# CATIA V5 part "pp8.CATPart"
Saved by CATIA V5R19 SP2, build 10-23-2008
Part number: pp8
Bounding box of the stored display mesh (mm): x -20 to 20, y 0 to 120, z -75.031 to 75.031
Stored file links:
  C:\Users\Welcome\Documents\thinkm2\pp8.CATPart
  C:\Users\Welcome\Documents\thinkm2\Brasmeca.CATProduct
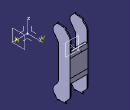
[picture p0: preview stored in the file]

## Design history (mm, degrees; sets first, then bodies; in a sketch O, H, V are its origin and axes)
AxisSystem1: origin (0, 0, 0), X (1, 0, 0), Y (0, 1, 0), Z (0, 0, 1)
Set1
  Line1: linked copy from another document
  Point1: linked copy from another document
Body1 (main body)
  Plane1: type Normal, Curve Line1, RefPoint Point1
  Plane2: type Offset, RefPlane YZ plane of AxisSystem1, Offset 20
  Sketch1 on Plane2, origin (20, 0, 0), H (0, 1, 0), V (0, 0, 1)
    line L1 (115.6767, 19.4458) -> (115.6767, 54.1125)
    line L2 (112.2785, 61.8229) -> (104.423, 69.6832)
    line L3 (104.423, 69.6832) -> (106.9485, 72.2071)
    line L4 (106.9485, 72.2071) -> (88.0918, 72.9515)
    line L5 (88.0918, 72.9515) -> (88.0918, 75.0312)
    line L6 (88.0918, 75.0312) -> (79.7197, 65.0499)
    line L7 (79.5179, 51.5719) -> (86.7623, 42.3901)
    line L8 (89.7249, 33.8522) -> (89.7249, 13.8264)
    arc A1 centre (103.978, 53.5605) radius 11.7118 from (115.6767, 54.1125) to (112.2785, 61.8229) ccw
    arc A2 centre (87.9019, 58.1869) radius 10.6794 from (79.7197, 65.0499) to (79.5179, 51.5719) ccw
    arc A3 centre (75.9411, 33.8522) radius 13.7839 from (86.7623, 42.3901) to (89.7249, 33.8522) cw
    line L9 (89.7249, -33.8522) -> (89.7249, -13.8264)
    arc A4 centre (75.9411, -33.8522) radius 13.7839 from (86.7623, -42.3901) to (89.7249, -33.8522) ccw
    line L10 (79.5179, -51.5719) -> (86.7623, -42.3901)
    arc A5 centre (87.9019, -58.1869) radius 10.6794 from (79.7197, -65.0499) to (79.5179, -51.5719) cw
    line L11 (88.0918, -75.0312) -> (79.7197, -65.0499)
    line L12 (88.0918, -72.9515) -> (88.0918, -75.0312)
    line L13 (106.9485, -72.2071) -> (88.0918, -72.9515)
    line L14 (104.423, -69.6832) -> (106.9485, -72.2071)
    line L15 (112.2785, -61.8229) -> (104.423, -69.6832)
    arc A6 centre (103.978, -53.5605) radius 11.7118 from (115.6767, -54.1125) to (112.2785, -61.8229) cw
    line L16 (115.6767, -19.4458) -> (115.6767, -54.1125)
    line L17 (89.7249, 13.8264) -> (89.7249, -13.8264)
    line L18 (115.6767, 19.4458) -> (115.6767, -19.4458)
  Sketch2 on Plane1, origin (0, 100, 0), H (-1, 0, 0), V (0, 0, 1)
    line L1 (-18, 90) -> (-18, 30)
    line L2 (-18, 30) -> (18, 30)
    line L3 (18, 30) -> (18, 90)
    line L4 (18, -30) -> (-18, -30)
    line L5 (-18, -30) -> (-18, -90)
    line L6 (18, -30) -> (18, -90)
    line L7 (18, -90) -> (20, -90)
    line L8 (-18, -90) -> (-20, -90)
    line L9 (18, 90) -> (20, 90)
    line L10 (-18, 90) -> (-20, 90)
    line L11 (20, 90) -> (20, -90)
    line L12 (-20, 90) -> (-20, -90)
    length L2 = 36
    length L4 = 36
    distance L2 H = 30
    distance L4 H = 30
    distance L6 V = 18
    distance L3 V = 18
    distance L11 V = 20
    distance L12 V = 20
  SolidCombine1: FirstComponentProfile Sketch1, FirstComponentDirection Sketch1, SecondComponentProfile Sketch2, SecondComponentDirection Sketch2
  Sketch3 on face of SolidCombine1 from Sketch1.L17, origin (0, 89.7249, 0), H (1, 0, 0), V (0, 0, 1)
    line L1 (-18, 30) -> (18, 30)
    line L2 (18, 30) -> (18, -30)
    line L3 (18, -30) -> (-18, -30)
    line L4 (-18, -30) -> (-18, 30)
    distance L2 V = 18
    distance L2 L4 = 36
    distance L1 H = 30
    distance L1 L3 = 60
  Pocket1: profile Sketch3, direction (0, 1, 0), length 21
  Sketch4 on face of SolidCombine1 from Sketch1.L1, origin (0, 115.6767, 0), H (-1, 0, 0), V (0, 0, 1)
    line L1 (-20, 30) -> (20, 30)
    line L2 (20, 30) -> (20, 26)
    line L3 (20, 26) -> (-20, 26)
    line L4 (-20, 26) -> (-20, 30)
    distance L2 L4 = 40
    distance L2 V = 20
    distance L1 H = 30
    length L2 = 4
  Sketch5 on XY plane of AxisSystem1, origin (0, 0, 0), H (1, 0, 0), V (0, 1, 0)
    line L1 (-20.0631, 115.7358) -> (-10.7881, 139.0037)
    line L2 (-7.1303, 144.5219) -> (-5.016, 146.6111)
    line L3 (20.0631, 115.7358) -> (10.9745, 138.536)
    line L4 (6.7722, 144.8758) -> (5.1256, 146.5028)
    line L5 (1.2636, 148.089) -> (-1.4176, 148.089)
    arc A1 centre (-6.2937, 131.6525) radius 18.5896 from (10.9745, 138.536) to (6.7722, 144.8758) ccw
    arc A2 centre (4.2424, 133.0122) radius 16.1806 from (-7.1303, 144.5219) to (-10.7881, 139.0037) ccw
    arc A3 centre (1.2636, 142.5944) radius 5.4946 from (1.2636, 148.089) to (5.1256, 146.5028) cw
    arc A4 centre (-1.4176, 142.9694) radius 5.1196 from (-1.4176, 148.089) to (-5.016, 146.6111) ccw
    line L6 (20.0631, 115.7358) -> (-20.0631, 115.7358)
  Sketch6 on XY plane of AxisSystem1, origin (0, 0, 0), H (1, 0, 0), V (0, 1, 0)
  Sketch7 on XY plane of AxisSystem1, origin (0, 0, 0), H (1, 0, 0), V (0, 1, 0)
  SolidCombine2: FirstComponentProfile Sketch5, FirstComponentDirection Sketch5, SecondComponentProfile Sketch4, SecondComponentDirection Sketch4
  Mirror1: of SolidCombine2, Sketch5, Sketch4, about XY plane of AxisSystem1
